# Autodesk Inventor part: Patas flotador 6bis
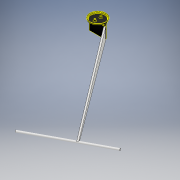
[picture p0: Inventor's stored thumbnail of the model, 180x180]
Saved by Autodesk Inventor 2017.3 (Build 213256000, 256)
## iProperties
Part Number: Patas flotador 6bis
Material: Plástico ABS
Document SubType Name: Modeling
Designer: PABLO HERNANDEZ
Density: 1.06 g/cm^3
Appearance: Suave - Blanco
Mass: 4.28877 g
Surface Area: 39.5254 cm^2
Volume: 4.04601 cm^3
Author: M.RICO
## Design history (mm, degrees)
sketch "Boceto1"
  geometry: C1 r 16 at (0, 0); 1 further point
  constraints: 1 centre point, 1 coincident
  dimensions: "d0" = 32 diameter of C1
extrude "Extrusión1" new body sketch "Boceto1" distance "d1" = 1; taper "d2" = 0 deg; dims "d93" = 1, "d94" = 0
sketch "Boceto2"
  geometry: C1 r 16 at (0, 0); C2 r 15 at (0, 0); C3 r 14 at (0, 0); 1 further point
  constraints: 3 centre point, 1 coincident
  dimensions: "d3" = 1 radial gap between concentric circles of C1 C2; "d4" = 1 radial gap between concentric circles of C2 C3
extrude "Extrusión2" join sketch "Boceto2" distance "d5" = 3; taper "d6" = 0 deg
sketch "Boceto3"
  geometry: C1 r 15 at (0, 0); C2 r 14 at (0, 0); 1 further point
  constraints: 2 centre point, 1 coincident
  dimensions: "d7" = 1 radial gap between concentric circles of C1 C2; "d123" = 30 diameter of C1
extrude "Extrusión3" join sketch "Boceto3" distance "d8" = 2; taper "d9" = 0 deg
sketch "Boceto4"
  geometry: C1 r 16 at (0, 0); 1 further point
  constraints: 1 centre point, 1 coincident
extrude "Extrusión4" cut sketch "Boceto4" distance "d10" = 0.5; taper "d11" = 0 deg
sketch "Boceto7"
  geometry: L1 (1.5, -15.93)-(1.5, 15.93); L2 (-1.5, -15.93)-(-1.5, 15.93); A1 r 16 centre (0, 0) between (1.5, 15.93) and (-1.5, 15.93); A2 r 16 centre (0, 0) between (-1.5, -15.93) and (1.5, -15.93); 2 further points
  constraints: 4 end point, 4 point on circle, 2 centre point, 1 coincident
extrude "Extrusión7" join sketch "Boceto7" distance "d63" = 25; taper "d64" = 0 deg
fillet "Empalme2" dims "d95" = 3
fillet "Empalme3" dims "d96" = 0.5
sketch "Boceto13"
  geometry: C1 r 1.2 at (-6, 0) reference; C2 r 1.75 at (-6, 0); C3 r 1.2 at (6, 0) reference; C4 r 1.75 at (6, 0); 1 further point
  constraints: 2 centre point, 2 coincident
  dimensions: "d118" = 3.5 diameter of C2; "d119" = 3.5 diameter of C4
extrude "Extrusión10" join sketch "Boceto13" distance "d120" = 3; taper "d121" = 0 deg
fillet "Empalme4" dims "d122" = 1
sketch "Boceto14"
  geometry: 1 further point
sketch "Boceto15"
  geometry: C1 r 1.2 at (6, 0) reference; C2 r 2.5 at (6, 0); C3 r 1.2 at (-6, 0) reference; C4 r 2.5 at (-6, 0); 1 further point
  constraints: 2 centre point, 2 coincident
  dimensions: "d124" = 5 diameter of C2; "d125" = 5 diameter of C4
extrude "Extrusión11" cut sketch "Boceto15" distance "d126" = 10; taper "d127" = 0 deg
hole "Agujero7" diameter "d151" = 2.4; stored, may be unused: countersink angle "d155" = 90 deg, drill point angle "d157" = 118 deg; dims "d149" = 10, "d150" = 10, "d152" = 6, "d153" = 4, "d154" = 2, "d156" = 8
hole "Agujero8" diameter "d160" = 2.4; stored, may be unused: countersink angle "d164" = 90 deg, drill point angle "d166" = 118 deg; dims "d158" = 10, "d159" = 10, "d161" = 6, "d162" = 4, "d163" = 2, "d165" = 8
node "Eje de trabajo1"
feature "Desplazar cuerpo1"
feature "Compuesta1"
feature "Desplazar cuerpo2"
node "Eje de trabajo2"
feature "Desplazar cuerpo3"
node "Plano de trabajo6"
sketch "Boceto27"
  geometry: L1 (0, 0)-(-149.324, -102.291); L2 (-134.431, -229.557)-(132.044, -87.232); C1 r 14 at (-149.324, -102.291) reference
  constraints: 4 end point
node "Plano de trabajo7"
node "Plano de trabajo8"
sketch "Boceto28"
  geometry: C1 r 2 at (0, 0); 1 further point
  constraints: 1 centre point
  dimensions: "d177" = 4 diameter of C1
extrude "Extrusión14" join sketch "Boceto28" stored distance "d178" = 10; taper "d179" = 0 deg
sketch "Boceto29"
  geometry: L1 (-0.28, 0)-(0, 0) reference; L2 (0, 0)-(-102.216, -91.987); L3 (-0.28, 23.165)-(-0.28, 0) reference; L4 (0, 23.165)-(0, 0) reference; L5 (0, 0)-(0, 23.165); L6 (0, 23.165)-(-105.015, -89.134); C1 r 2 at (-103.554, -90.5) reference; A1 r 2 centre (-103.554, -90.5) between (-102.216, -91.987) and (-105.015, -89.134) reference; 1 further point
  constraints: 6 end point, 2 point on circle, 2 tangent, 1 collinear
extrude "Extrusión15" join sketch "Boceto29" stored distance "d180" = 10; taper "d181" = 0 deg
node "Plano de trabajo9"
sketch "Boceto30"
  geometry: L1 (1.356, 23.165)-(1.356, 0) reference; L2 (1.356, 0)-(-130.469, -92.139); L3 (1.356, 0)-(1.356, 23.165); L4 (1.356, 23.165)-(-132.897, -88.965); A1 r 2 centre (-131.615, -90.5) between (-130.469, -92.139) and (-132.897, -88.965) reference; A2 r 2 centre (-131.615, -90.5) between (-132.897, -88.965) and (-130.469, -92.139); 1 further point
  constraints: 6 end point, 4 point on circle, 2 tangent, 1 centre point, 1 coincident, 1 vertical
extrude "Extrusión16" join sketch "Boceto30" distance "d182" = 3; taper "d183" = 0 deg
node "Plano de trabajo10"
sketch "Boceto31"
  geometry: L1 (-7.175, -6.405)-(170.651, -6.405); L2 (170.651, -6.405)-(170.651, 129.955); L3 (170.651, 129.955)-(-7.175, 129.955); L4 (-7.175, 129.955)-(-7.175, -6.405); 1 further point
  constraints: 8 end point, 2 parallel, 1 horizontal, 1 perpendicular
extrude "Extrusión17" cut sketch "Boceto31" distance "d185" = 150; taper "d186" = 0 deg
sketch "Boceto32"
  geometry: C1 r 1 at (0, 0); 1 further point
  constraints: 1 centre point
  dimensions: "d187" = 2 diameter of C1
extrude "Extrusión18" cut sketch "Boceto32" distance "d188" = 6; taper "d189" = 0 deg
node "Sólido1"
node "Sup1"
other parameters: "sa_0" = 4, "d167" = 90 deg, "d168" = -149.324, "d169" = -102.291, "d170" = 0, "d171" = 9.86699, "d184" = 147
